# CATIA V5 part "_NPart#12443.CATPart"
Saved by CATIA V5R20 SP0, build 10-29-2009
Part number: DIN6325 Ø2,5X20_Parallel Pin ISO 2338 - 2.5 h6 x 20 - St
Revision: ANY
Definition: UNKNOWN
Nomenclature: DIN6325 Ø2,5X20_Parallel Pin ISO 2338 - 2.5 h6 x 20 - St
Source: Unknown
Bounding box of the stored display mesh (mm): x 0 to 20, y -1.25 to 1.25, z -1.25 to 1.25
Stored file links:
  C:\Users\Utente\Desktop\IO LAVORO\3D X SITO CF\CUMSA\3D files AE\AE 031620\_NPart#12443.CATPart
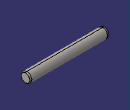
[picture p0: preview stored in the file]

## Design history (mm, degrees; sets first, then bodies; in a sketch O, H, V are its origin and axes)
Body1 "Base-Revolve" (main body)
  Solid1: solid without history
